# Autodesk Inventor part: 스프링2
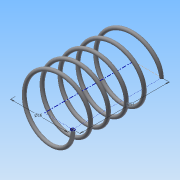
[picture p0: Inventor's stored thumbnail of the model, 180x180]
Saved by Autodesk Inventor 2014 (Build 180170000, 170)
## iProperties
Created: 2015-06
Part Number: 스프링2
Material: 강철, 연강
Document SubType Name: Modeling
Designer: Administrator
Density: 7.86 g/cm^3
Appearance: 강철
Mass: 1.5292 g
Surface Area: 7.8715 cm^2
Volume: 0.194555 cm^3
Author: Administrator
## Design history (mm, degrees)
sketch "스케치1"
  geometry: L1 (0, 0)-(8, 0); L2 (8, 0)-(8, 14.5); L3 (8, 14.5)-(0, 14.5); L4 (0, 14.5)-(0, 0); C1 r 0.5 at (8, 0)
  constraints: 8 end point, 2 parallel, 1 centre point, 1 coincident, 1 horizontal, 1 perpendicular
  dimensions: "d1" = 1 diameter of C1; "d2" = 16 diameter of L2 L4; "d3" = 14.5 distance of L1.end L2.end (derived)
feature "코일1" sketch "스케치1" pitch "d4" = 10; turns "d6" = 5; dims "d5" = 14.5 (= d3), "d7" = 0, angle "d8" = 90 deg, angle "d9" = 90 deg, "d10" = 0, "d11" = 0
sketch "스케치2"
  geometry: L1 (-8.5, 0)-(-7.5, 0) reference; 1 further point
  constraints: 1 horizontal alignment
extrude "돌출1" cut sketch "스케치2" stored distance "d12" = 10; taper "d13" = 0 deg
node "작업 평면1"
sketch "스케치3"
  geometry: L1 (8.5, 0)-(7.5, 0) reference; 1 further point
  constraints: 1 horizontal alignment
extrude "돌출2" cut sketch "스케치3" stored distance "d15" = 10; taper "d16" = 0 deg
node "솔리드1"
node "절단 모서리 투영1"
node "절단 모서리 투영2"
other parameters: "d14" = -14.5 (= -d3)
